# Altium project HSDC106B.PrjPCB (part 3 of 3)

## Sheet HSDC106B_EVM_DP83561_64p_EZFET.SchDoc
size 431 x 279 mm; Date: Not shown in title block; ApprovedBy: Not shown in title block; CheckedBy: Not shown in title block; Author: Not shown in title block; CompanyName: Not shown in title block; DrawnBy: Justin Lazaruk; Engineer: Not shown in title block; Organization: Not shown in title block; Address1: Not shown in title block; Address2: Not shown in title block; Address3: Not shown in title block; Address4: Not shown in title block; DocumentNumber: 8; Revision: Use project parameter SCH_Rev; SheetNumber: 8; SheetTotal: 9; PageSetup: Record=PageOptions¦CenterHorizontal=True¦CenterVertical=True¦PrintScale=1.00¦XCorrection=1.00¦YCorrection=1.00¦PrintKind=0¦BorderSize=5000000¦LeftOffset=0¦BottomOffset=0¦Orientation=2¦PaperLength=1000¦PaperWidth=1000¦Scale=100¦PaperSource=15¦PrintQuality=600¦MediaType=1¦DitherType=10¦PaperKind=Letter¦PrintScaleMode=1
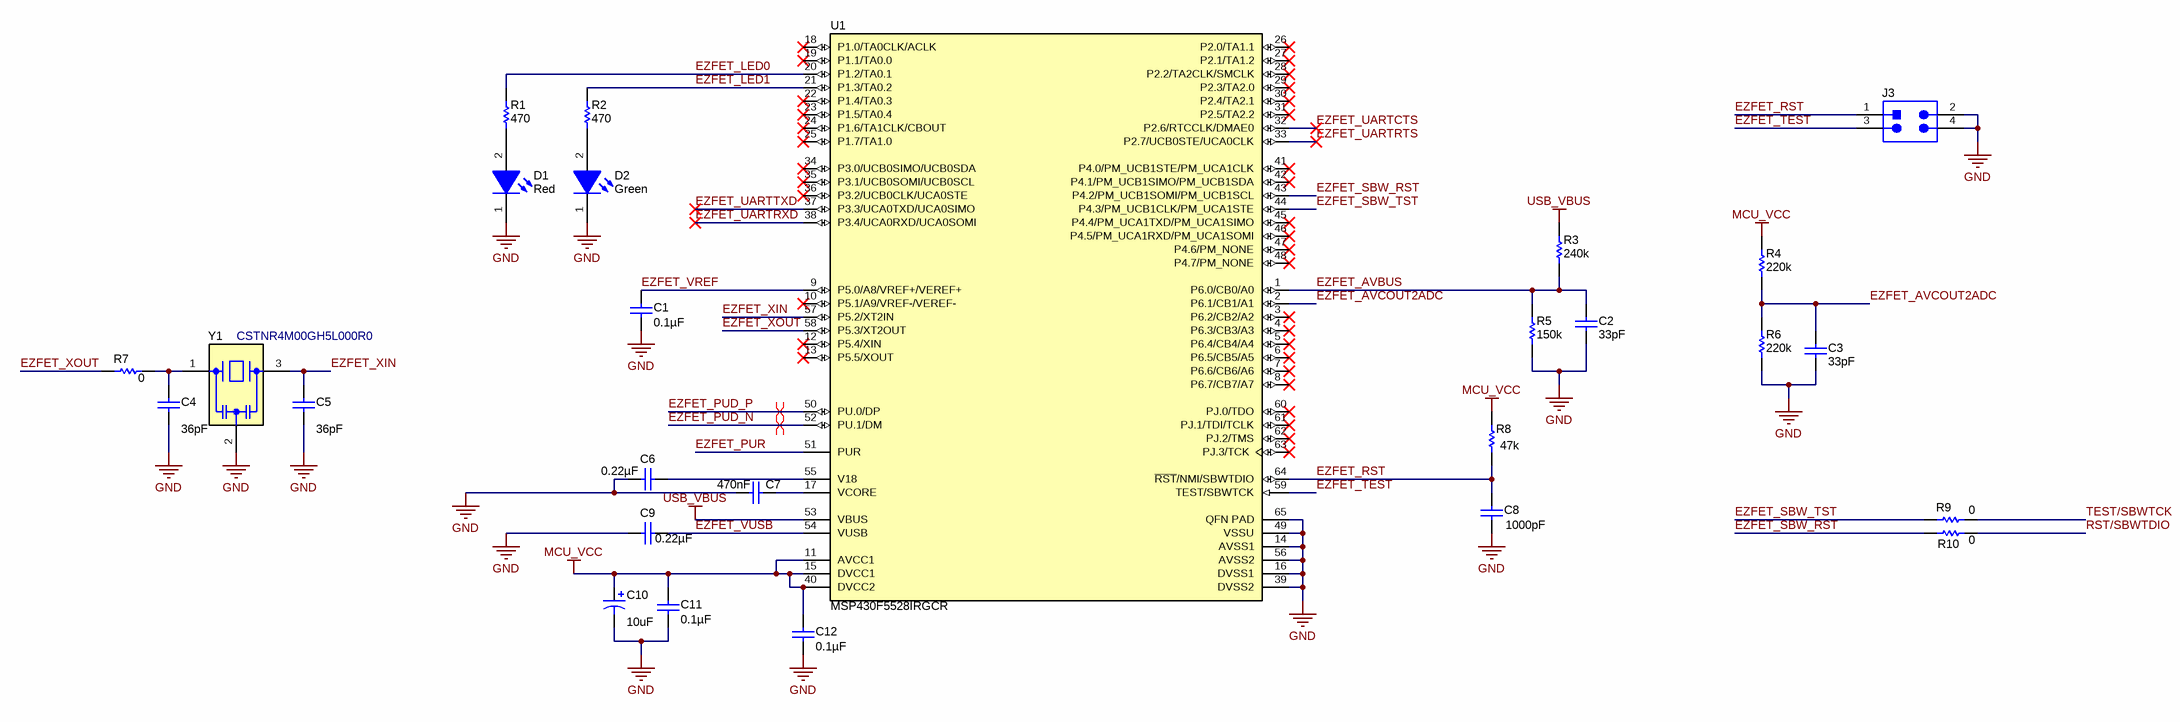
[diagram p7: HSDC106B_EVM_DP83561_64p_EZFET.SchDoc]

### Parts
C1  ValueDisplayed: 0.1µF  [0402]  (hidden comment: CL05B104KO5NNNC)
C2  ValueDisplayed: 33pF  [0402]  (hidden comment: 885012005043)
C3  ValueDisplayed: 33pF  [0402]  (hidden comment: 885012005043)
C4  ValueDisplayed: 36pF  [0402]  (hidden comment: CL05C360JB5NNNC)
C5  ValueDisplayed: 36pF  [0402]  (hidden comment: CL05C360JB5NNNC)
C6  ValueDisplayed: 0.22µF  [0603]  (hidden comment: CL10A224KB8NNNC)
C7  Cap_F: 470nF  [0603]  (hidden comment: CGA3E3X7R1H474K080AB)
C8  ValueDisplayed: 1000pF  [0402]  (hidden comment: GRM1555C1H102JA01D)
C9  ValueDisplayed: 0.22µF  [0603]  (hidden comment: CL10A224KB8NNNC)
C10  ValueDisplayed: 10uF  [7343-31]  (hidden comment: TPSD106K035R0125)
C11  ValueDisplayed: 0.1µF  [0402]  (hidden comment: CL05B104KO5NNNC)
C12  ValueDisplayed: 0.1µF  [0402]  (hidden comment: CL05B104KO5NNNC)
D1  value Red  [WL-SMCW_RED]  (hidden comment: 150060RS75000)
D2  value Green  [WL-SMCD-0603]  (hidden comment: 150060VS55040)
J3  TSW-102-07-G-D  [TSW-102-07-G-D]  (value not drawn)
R1  ValueDisplayed: 470  [0402]  (hidden comment: CRCW0402470RJNED)
R2  ValueDisplayed: 470  [0402]  (hidden comment: CRCW0402470RJNED)
R3  ValueDisplayed: 240k  [0402]  (hidden comment: CRCW0402240KJNED)
R4  ValueDisplayed: 220k  [0402]  (hidden comment: CRCW0402220KJNED)
R5  ValueDisplayed: 150k  [0402]  (hidden comment: CRCW0402150KJNED)
R6  ValueDisplayed: 220k  [0402]  (hidden comment: CRCW0402220KJNED)
R7  ValueDisplayed: 0  [0402]  (hidden comment: RC0402JR-070RL)
R8  ValueDisplayed: 47k  [0402]  (hidden comment: CRCW040247K0JNED)
R9  ValueDisplayed: 0  [0402]  (hidden comment: RC0402JR-070RL)
R10  ValueDisplayed: 0  [0402]  (hidden comment: RC0402JR-070RL)
U1  MSP430F5528IRGCR  [RGC0064B]
Y1  CSTNR4M00GH5L000R0  [MuRata_CSTNR]

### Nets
GND: C1.2 C2.2 C3.2 C4.2 C5.2 C6.2 C7.2 C8.2 C9.2 C10.2(-) C11.2 C12.2 D1.1(K) D2.1(K) J3.2 J3.4 R5.1 R6.1 U1.14(AVSS1) U1.16(DVSS1) U1.39(DVSS2) U1.49(VSSU) U1.56(AVSS2) U1.65(QFN_PAD) Y1.2(GND)
MCU_VCC: C10.1(+) C11.1 C12.1 R4.2 R8.2 U1.11(AVCC1) U1.15(DVCC1) U1.40(DVCC2)
USB_VBUS: R3.2 U1.53(VBUS)
EZFET_AVBUS: C2.1 R3.1 R5.2 U1.1(P6.0/CB0/A0)
EZFET_AVCOUT2ADC: C3.1 R4.1 R6.2 U1.2(P6.1/CB1/A1)
EZFET_LED0: R1.2 U1.20(P1.2/TA0.1)
EZFET_LED1: R2.2 U1.21(P1.3/TA0.2)
EZFET_PUD_N: U1.52(PU.1/DM)
EZFET_PUD_P: U1.50(PU.0/DP)
EZFET_PUR: U1.51(PUR)
EZFET_RST: C8.1 J3.1 R8.1 U1.64(~{RST}/NMI/SBWTDIO)
EZFET_SBW_RST: R10.1 U1.43(P4.2/PM_UCB1SOMI/PM_UCB1SCL)
EZFET_SBW_TST: R9.1 U1.44(P4.3/PM_UCB1CLK/PM_UCA1STE)
EZFET_TEST: J3.3 U1.59(TEST/SBWTCK)
EZFET_UARTCTS: U1.32(P2.6/RTCCLK/DMAE0)
EZFET_UARTRTS: U1.33(P2.7/UCB0STE/UCA0CLK)
EZFET_UARTRXD: U1.38(P3.4/UCA0RXD/UCA0SOMI)
EZFET_UARTTXD: U1.37(P3.3/UCA0TXD/UCA0SIMO)
EZFET_VREF: C1.1 U1.9(P5.0/A8/VREF+/VEREF+)
EZFET_VUSB: C9.1 U1.54(VUSB)
EZFET_XIN: C5.1 U1.57(P5.2/XT2IN) Y1.3(Out)
EZFET_XOUT: R7.1 U1.58(P5.3/XT2OUT)
RST/SBWTDIO: R10.2
TEST/SBWTCK: R9.2
NetC4_1: C4.1 R7.2 Y1.1(In)
NetC6_1: C6.1 U1.55(V18)
NetC7_1: C7.1 U1.17(VCORE)
NetD1_2: D1.2(A) R1.1
NetD2_2: D2.2(A) R2.1

Not connected (* = marked no-connect by the designer): U1 3(P6.2/CB2/A2)* 4(P6.3/CB3/A3)* 5(P6.4/CB4/A4)* 6(P6.5/CB5/A5)* 7(P6.6/CB6/A6)* 8(P6.7/CB7/A7)* 10(P5.1/A9/VREF-/VEREF-)* 12(P5.4/XIN)* 13(P5.5/XOUT)* 18(P1.0/TA0CLK/ACLK)* 19(P1.1/TA0.0)* 22(P1.4/TA0.3)* 23(P1.5/TA0.4)* 24(P1.6/TA1CLK/CBOUT)* 25(P1.7/TA1.0)* 26(P2.0/TA1.1)* 27(P2.1/TA1.2)* 28(P2.2/TA2CLK/SMCLK)* 29(P2.3/TA2.0)* 30(P2.4/TA2.1)* 31(P2.5/TA2.2)* 34(P3.0/UCB0SIMO/UCB0SDA)* 35(P3.1/UCB0SOMI/UCB0SCL)* 36(P3.2/UCB0CLK/UCA0STE)* 41(P4.0/PM_UCB1STE/PM_UCA1CLK)* 42(P4.1/PM_UCB1SIMO/PM_UCB1SDA)* 45(P4.4/PM_UCA1TXD/PM_UCA1SIMO)* 46(P4.5/PM_UCA1RXD/PM_UCA1SOMI)* 47(P4.6/PM_NONE)* 48(P4.7/PM_NONE)* 60(PJ.0/TDO)* 61(PJ.1/TDI/TCLK)* 62(PJ.2/TMS)* 63(PJ.3/TCK)*

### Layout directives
differential pair: EZFET_PUD_N, EZFET_PUD_P

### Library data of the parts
C1 C11 C12 = CMP-0085850-1: CAP, CERM, 0.1 µF, 16 V,+/- 10%, X7R, 0402; Manufacturer: Walsin; SizeZ_mm: 0.6; SizeX_mm: 1; AEC Category: Q200; AEC Qualified: N; SizeY_mm: 0.5; VDC_V: 16V; Value: 0.1uF; Cap_F: 100nF; U/M: EA; SizeAreaWB_mm2: 3; TaMin_C: -55°C; TaMax_C: 125°C
C2 C3 = CMP-0006213-2: CAP, CERM, 33 pF, 25 V, +/- 5%, C0G/NP0, 0402; Manufacturer: Wurth Elektronik; TaMin_C: -55°C; Polarized: N; SizeAreaWB_mm2: 3; Value1: Unknown; U/M: EA; Value: 33pF; TaMax_C: 125°C; SizeZ_mm: 0.6; SizeX_mm: 1; SizeY_mm: 0.5; Value2: 25V; AEC Category: Q200
C4 C5 = CMP-0083839-1: CAP, CERM, 36 pF, 50 V,+/- 5%, C0G/NP0, 0402; Manufacturer: Samsung Electro-Mechanics; SizeAreaWB_mm2: 3; SizeArea_mm2: 0.5; AEC Qualified: N; AEC Category: Q200; Value: 36pF; TaMax_C: 125°C; SizeZ_mm: 0.6; TaMin_C: -55°C; VDC_V: 50V; U/M: EA; SizeX_mm: 1
C6 C9 = CMP-0860899-1: CAP, CERM, 0.22 µF, 50 V,+/- 10%, X5R, 0603; Manufacturer: Samsung Electro-Mechanics; Cap_F: 220nF; U/M: EA; TaMax_C: 85°C; SizeAreaWB_mm2: 4.68; VDC_V: 50V; Value: 0.22uF; Polarized: N; AEC Category: Q200; SizeArea_mm2: 1.28; SizeY_mm: 0.8; SizeX_mm: 1.6; TaMin_C: -55°C; SizeZ_mm: 1
C7 = CMP-0007096-4: CAP, CERM, 0.47 uF, 50 V, +/- 10%, X7R, AEC-Q200 Grade 1, 0603; Manufacturer: TDK; TaMin_C: -55°C; ESR_ohm: 0.01064; Polarized: N; SizeAreaWB_mm2: 4.68; Value1: 0.01064 ohm; U/M: EA; Value: 0.47uF; TaMax_C: 125°C; SizeZ_mm: 1; SizeX_mm: 1.6; SizeY_mm: 0.8; Value2: 50V; SizeArea_mm2: 1.28; AEC Qualified: Y; IRMS_A: 1.59966A; AEC Category: Q200
C8 = CMP-0006412-2: CAP, CERM, 1000 pF, 50 V, +/- 5%, C0G/NP0, 0402; Manufacturer: MuRata; TaMin_C: -55°C; Polarized: N; SizeAreaWB_mm2: 3; Value1: Unknown; U/M: EA; Value: 1000pF; TaMax_C: 125°C; SizeZ_mm: 0.6; SizeX_mm: 1; SizeY_mm: 0.5; Value2: 50V; Cap_F: 1nF; AEC Category: Q200
C10 = CMP-0011855-2: CAP, TA, 10 uF, 35 V, +/- 10%, 0.125 ohm, SMD; Manufacturer: AVX; TaMin_C: -55°C; ESR_ohm: 0.125; Polarized: Y; SizeAreaWB_mm2: 58.59; U/M: EA; Value: 10uF; TaMax_C: 125°C; SizeZ_mm: 3.1; SizeX_mm: 7.3; SizeY_mm: 4.3; Cap_Case: D; Value2: 35V; SizeArea_mm2: 31.39; CompType: Capacitor; Cap_F: 10µF; IRMS_A: 986mA; AEC Category: Q200
D1 = CMP-0002947-3: LED, Red, SMD; Manufacturer: Wurth Elektronik; Value1: 0.072W; Vf_V: 2V; Angle: 140; Tjmax_C: 85°C; Type: AlInGaP; Vr_V: 5V; Io_A: 30mA; Power_TotalModule: 72mW
D2 = CMP-0081648-2: LED, Green, SMD; Manufacturer: Wurth Elektronik; Type: AlInGaP; Vr_V: 5V; SizeZ_mm: 0.5; Tjmax_C: 115°C; Io_A: 20mA; Value1: 0.048W; Vf_V: 2V; SizeArea_mm2: 1.28; Angle: 140; SizeX_mm: 1.6; Ir_A: 10µA; Power_TotalModule: 48mW; SizeAreaWB_mm2: 4.68; SizeY_mm: 0.8
J3 = CMP-0075404-1: Header, 100mil, 2x2, Gold, TH; Manufacturer: Samtec; Pitch_mm: 2.54; Cert_VDE: N; Gender: Male; Cert_CSA: Y; Voltage_V: 550V; Green_REACh: Passed; Current_A: 6.3A; CT: False; Green_Lifecycle: Active; Row_Count: 2; CNHeader: True
R1 R2 = CMP-0026934-3: RES, 470, 5%, 0.063 W, AEC-Q200 Grade 0, 0402; Manufacturer: Vishay-Dale; Power_W: 63mW; TempCo: 200 ppm/C; Value_Code: 470R; Value: 470; EIA_Code: E24; SizeX_mm: 1; SizeY_mm: 0.5; SizeZ_mm: 0.6; Value2: 0.063W; AEC Qualified: Y; VDC_V: 50V; AEC Category: Q200; AEC Grade: 0
R3 = CMP-0026881-2: RES, 240 k, 5%, 0.063 W, AEC-Q200 Grade 0, 0402; Manufacturer: Vishay-Dale; Power_W: 63mW; TempCo: 200 ppm/C; Value: 240k; EIA_Code: E24; SizeX_mm: 1; SizeY_mm: 0.5; SizeZ_mm: 0.6; Value2: 0.063W; AEC Qualified: Y; VDC_V: 50V; AEC Category: Q200; AEC Grade: 0
R4 R6 = CMP-0026877-2: RES, 220 k, 5%, 0.063 W, AEC-Q200 Grade 0, 0402; Manufacturer: Vishay-Dale; Power_W: 63mW; TempCo: 200 ppm/C; Value: 220k; EIA_Code: E24; SizeX_mm: 1; SizeY_mm: 0.5; SizeZ_mm: 0.6; Value2: 0.063W; AEC Qualified: Y; VDC_V: 50V; AEC Category: Q200; AEC Grade: 0
R5 = CMP-0026840-2: RES, 150 k, 5%, 0.063 W, AEC-Q200 Grade 0, 0402; Manufacturer: Vishay-Dale; Power_W: 63mW; TempCo: 200 ppm/C; Value: 150k; EIA_Code: E24; SizeX_mm: 1; SizeY_mm: 0.5; SizeZ_mm: 0.6; Value2: 0.063W; AEC Qualified: Y; VDC_V: 50V; AEC Category: Q200; AEC Grade: 0
R7 R9 R10 = CMP-0027004-2: RES, 0, 5%, 0.063 W, 0402; Manufacturer: Yageo America; Power_W: 63mW; TempCo: 200 ppm/C; Value_Code: 0000; U/M: EA; Value: 0; EIA_Code: E24; SizeX_mm: 1; SizeY_mm: 0.5; SizeZ_mm: 0.6; Value2: 0.063W; VDC_V: 50V; AEC Category: Q200
R8 = CMP-0026935-3: RES, 47 k, 5%, 0.063 W, AEC-Q200 Grade 0, 0402; Manufacturer: Vishay-Dale; Power_W: 63mW; TempCo: 200 ppm/C; Value_Code: 47k0; Value: 47k; EIA_Code: E24; SizeX_mm: 1; SizeY_mm: 0.5; SizeZ_mm: 0.6; Value2: 0.063W; AEC Qualified: Y; VDC_V: 50V; AEC Category: Q200; AEC Grade: 0
U1 = CMP-0039268-4: 16-Bit Ultra-Low-Power Microcontroller, 128KB Flash, 8KB RAM, USB, 12Bit ADC, 2 USCIs, 32Bit HW MPY, RGC0064B (VQFN-64); Manufacturer: Texas Instruments; ADC: 12-bit SAR; Flash(KB): 128; CompType: IC; USB: 1; Rating: Catalog; Frequency(MHz): 25; GPIO: 47; SVS: Yes; SizeAreaWB_mm2: 121.0; USCI_B (I2C & SPI): 2; DMA: 3; AEC Qualified: N; Timers - 16-bit: 4; SizeX_mm: 9.0; AEC Category: Q200; ADC Channels: 16; SizeArea_mm2: 81.0; Multiplier: 32x32; SRAM(B): 8192; SizeZ_mm: 1.0
Y1 = CMP-0085483-1: Oscillator, 4 MHz, 700 ppm, 39 pF, SMD; Manufacturer: MuRata; SizeArea_mm2: 9; Load Capacitance: 39 pF; SizeZ_mm: 1.2; AEC Category: Q200; Frequency Tolerance: 700 ppm; SizeX_mm: 4.5; SizeAreaWB_mm2: 16.5; TaMax_C: 85°C; TaMin_C: -20°C; SizeY_mm: 2; AEC Qualified: N; Frequency_Fixed: 4MHz

## Sheet HSDC106B_EVM_DP83561_64p_Breakout.SchDoc
size 431 x 279 mm; Date: Not shown in title block; ApprovedBy: Not shown in title block; CheckedBy: Not shown in title block; Author: Not shown in title block; CompanyName: Not shown in title block; DrawnBy: Justin Lazaruk; Engineer: Not shown in title block; Organization: Not shown in title block; Address1: Not shown in title block; Address2: Not shown in title block; Address3: Not shown in title block; Address4: Not shown in title block; DocumentNumber: 5; Revision: Use project parameter SCH_Rev; SheetNumber: 5; SheetTotal: 9; PageSetup: Record=PageOptions¦CenterHorizontal=True¦CenterVertical=True¦PrintScale=1.00¦XCorrection=1.00¦YCorrection=1.00¦PrintKind=0¦BorderSize=5000000¦LeftOffset=0¦BottomOffset=0¦Orientation=2¦PaperLength=1000¦PaperWidth=1000¦Scale=100¦PaperSource=15¦PrintQuality=600¦MediaType=1¦DitherType=10¦PaperKind=Letter¦PrintScaleMode=1
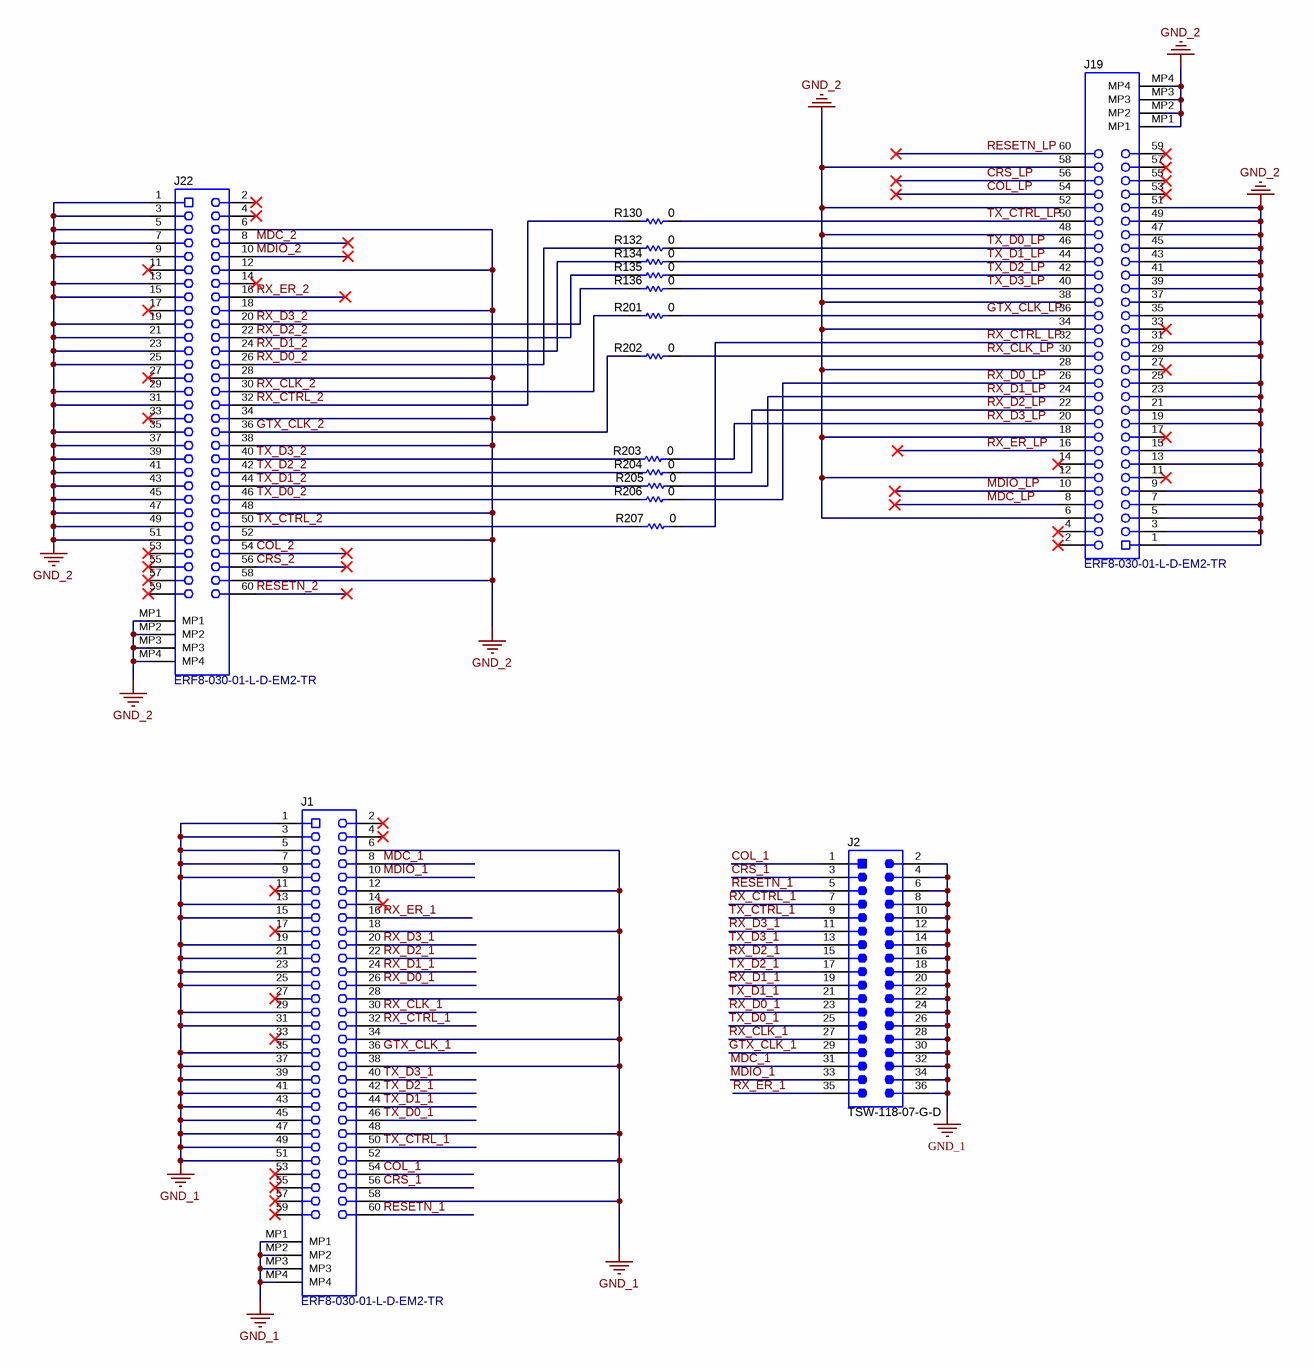
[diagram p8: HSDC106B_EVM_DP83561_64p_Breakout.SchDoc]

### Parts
J1  ERF8-030-01-L-D-EM2-TR  [Samtec_ERF8-030-01-x-D-EM2]
J2  TSW-118-07-G-D  [TSW-118-07-G-D]
J19  ERF8-030-01-L-D-EM2-TR  [Samtec_ERF8-030-01-x-D-EM2]
J22  ERF8-030-01-L-D-EM2-TR  [Samtec_ERF8-030-01-x-D-EM2]
R130  ValueDisplayed: 0  [0402]  (hidden comment: ERJ-2GE0R00X)
R132  ValueDisplayed: 0  [0402]  (hidden comment: ERJ-2GE0R00X)
R134  ValueDisplayed: 0  [0402]  (hidden comment: ERJ-2GE0R00X)
R135  ValueDisplayed: 0  [0402]  (hidden comment: ERJ-2GE0R00X)
R136  ValueDisplayed: 0  [0402]  (hidden comment: ERJ-2GE0R00X)
R201  ValueDisplayed: 0  [0402]  (hidden comment: ERJ-2GE0R00X)
R202  ValueDisplayed: 0  [0402]  (hidden comment: ERJ-2GE0R00X)
R203  ValueDisplayed: 0  [0402]  (hidden comment: ERJ-2GE0R00X)
R204  ValueDisplayed: 0  [0402]  (hidden comment: ERJ-2GE0R00X)
R205  ValueDisplayed: 0  [0402]  (hidden comment: ERJ-2GE0R00X)
R206  ValueDisplayed: 0  [0402]  (hidden comment: ERJ-2GE0R00X)
R207  ValueDisplayed: 0  [0402]  (hidden comment: ERJ-2GE0R00X)

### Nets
GND_1: J1.1 J1.3 J1.5 J1.6 J1.7 J1.9 J1.12 J1.13 J1.15 J1.18 J1.19 J1.21 J1.23 J1.25 J1.28 J1.29 J1.31 J1.34 J1.35 J1.37 J1.38 J1.39 J1.41 J1.43 J1.45 J1.47 J1.48 J1.49 J1.51 J1.52 J1.58 J1.MP1 J1.MP2 J1.MP3 J1.MP4 J2.2 J2.4 J2.6 J2.8 J2.10 J2.12 J2.14 J2.16 J2.18 J2.20 J2.22 J2.24 J2.26 J2.28 J2.30 J2.32 J2.34 J2.36
GND_2: J19.1 J19.3 J19.5 J19.6 J19.7 J19.9 J19.12 J19.13 J19.15 J19.18 J19.19 J19.21 J19.23 J19.25 J19.28 J19.29 J19.31 J19.34 J19.35 J19.37 J19.38 J19.39 J19.41 J19.43 J19.45 J19.47 J19.48 J19.49 J19.51 J19.52 J19.58 J19.MP1 J19.MP2 J19.MP3 J19.MP4 J22.1 J22.3 J22.5 J22.6 J22.7 J22.9 J22.12 J22.13 J22.15 J22.18 J22.19 J22.21 J22.23 J22.25 J22.28 J22.29 J22.31 J22.34 J22.35 J22.37 J22.38 J22.39 J22.41 J22.43 J22.45 J22.47 J22.48 J22.49 J22.51 J22.52 J22.58 J22.MP1 J22.MP2 J22.MP3 J22.MP4
COL_1: J1.54 J2.1
COL_2: J22.54
COL_LP: J19.54
CRS_1: J1.56 J2.3
CRS_2: J22.56
CRS_LP: J19.56
GTX_CLK_1: J1.36 J2.29
GTX_CLK_2: J22.36 R202.1
GTX_CLK_LP: J19.36 R201.2
MDC_1: J1.8 J2.31
MDC_2: J22.8
MDC_LP: J19.8
MDIO_1: J1.10 J2.33
MDIO_2: J22.10
MDIO_LP: J19.10
RESETN_1: J1.60 J2.5
RESETN_2: J22.60
RESETN_LP: J19.60
RX_CLK_1: J1.30 J2.27
RX_CLK_2: J22.30 R201.1
RX_CLK_LP: J19.30 R202.2
RX_CTRL_1: J1.32 J2.7
RX_CTRL_2: J22.32 R130.1
RX_CTRL_LP: J19.32 R207.2
RX_D0_1: J1.26 J2.23
RX_D0_2: J22.26 R132.1
RX_D0_LP: J19.26 R206.2
RX_D1_1: J1.24 J2.19
RX_D1_2: J22.24 R134.1
RX_D1_LP: J19.24 R205.2
RX_D2_1: J1.22 J2.15
RX_D2_2: J22.22 R135.1
RX_D2_LP: J19.22 R204.2
RX_D3_1: J1.20 J2.11
RX_D3_2: J22.20 R136.1
RX_D3_LP: J19.20 R203.2
RX_ER_1: J1.16 J2.35
RX_ER_2: J22.16
RX_ER_LP: J19.16
TX_CTRL_1: J1.50 J2.9
TX_CTRL_2: J22.50 R207.1
TX_CTRL_LP: J19.50 R130.2
TX_D0_1: J1.46 J2.25
TX_D0_2: J22.46 R206.1
TX_D0_LP: J19.46 R132.2
TX_D1_1: J1.44 J2.21
TX_D1_2: J22.44 R205.1
TX_D1_LP: J19.44 R134.2
TX_D2_1: J1.42 J2.17
TX_D2_2: J22.42 R204.1
TX_D2_LP: J19.42 R135.2
TX_D3_1: J1.40 J2.13
TX_D3_2: J22.40 R203.1
TX_D3_LP: J19.40 R136.2

Not connected (* = marked no-connect by the designer): J1 2* 4* 11* 14* 17* 27* 33* 53* 55* 57* 59*; J19 2* 4* 11* 14* 17* 27* 33* 53* 55* 57* 59*; J22 2* 4* 11* 14* 17* 27* 33* 53* 55* 57* 59*

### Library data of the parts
J1 J19 J22 = CMP-0055720-1: Receptacle, 0.8mm, 30x2, Gold, Edge Mount; Manufacturer: Samtec; CNHeader: FALSE; Current_A: 2.2A; Gender: Female; Voltage_V: 200V; CompType: Card Edge Socket; Row_Count: 2; Pitch_mm: 0.8; CT: TRUE; Cert_UL: Y
J2 = CMP-0075431-1: Header, 100mil, 18x2, Gold, TH; Manufacturer: Samtec; Pitch_mm: 2.54; Cert_VDE: N; Gender: Male; Cert_CSA: Y; Voltage_V: 550V; Green_REACh: Passed; Current_A: 6.3A; CT: False; Green_Lifecycle: Active; Row_Count: 2; CNHeader: True
R130 R132 R134-R136 R201-R207 = CMP-0026992-3: RES, 0, 5%, 0.1 W, AEC-Q200 Grade 0, 0402; Manufacturer: Panasonic; Power_W: 100mW; TempCo: 600 ppm/C; Value_Code: 0000; Value: 0; EIA_Code: E24; SizeX_mm: 1; SizeY_mm: 0.5; SizeZ_mm: 0.6; Value2: 0.1W; AEC Qualified: Y; VDC_V: 50V; AEC Category: Q200; SizeAreaWB_mm2: 3

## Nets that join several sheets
GND: HSDC106B_EVM_DP83561_64p_USB (43 pins), HSDC106B_EVM_DP83561_64p_Straps (8 pins), HSDC106B_EVM_DP83561_64p_PowerSupply (60 pins), HSDC106B_EVM_DP83561_64p_PHY (51 pins), HSDC106B_EVM_DP83561_64p_MSP430 (41 pins), HSDC106B_EVM_DP83561_64p_MAC_RJ45 (56 pins), HSDC106B_EVM_DP83561_64p_Hardware (7 pins), HSDC106B_EVM_DP83561_64p_EZFET (25 pins)
MCU_VCC: HSDC106B_EVM_DP83561_64p_USB (15 pins), HSDC106B_EVM_DP83561_64p_MSP430 (21 pins), HSDC106B_EVM_DP83561_64p_EZFET (8 pins)
RJ45_ERTH: HSDC106B_EVM_DP83561_64p_MAC_RJ45 (9 pins), HSDC106B_EVM_DP83561_64p_Hardware (M8.1)
USB_VBUS: HSDC106B_EVM_DP83561_64p_USB (5 pins), HSDC106B_EVM_DP83561_64p_PowerSupply (J21.1), HSDC106B_EVM_DP83561_64p_MSP430 (C19.2 U4.65), HSDC106B_EVM_DP83561_64p_EZFET (R3.2 U1.53)
VDDIO: HSDC106B_EVM_DP83561_64p_Straps (19 pins), HSDC106B_EVM_DP83561_64p_PowerSupply (5 pins), HSDC106B_EVM_DP83561_64p_PHY (17 pins), HSDC106B_EVM_DP83561_64p_MSP430 (R47.2 R48.2 R51.2)
AUTO_RECOVER: HSDC106B_EVM_DP83561_64p_Straps (J39.1), HSDC106B_EVM_DP83561_64p_PHY (J8.10 U5.34)
COL: HSDC106B_EVM_DP83561_64p_PHY (U5.32), HSDC106B_EVM_DP83561_64p_MAC_RJ45 (J6.1 R32.1)
CRS: HSDC106B_EVM_DP83561_64p_Straps (J41.1), HSDC106B_EVM_DP83561_64p_PHY (U5.33), HSDC106B_EVM_DP83561_64p_MAC_RJ45 (R33.1)
EZFET_PUD_N: HSDC106B_EVM_DP83561_64p_USB (C128.1 R196.1), HSDC106B_EVM_DP83561_64p_EZFET (U1.52)
EZFET_PUD_P: HSDC106B_EVM_DP83561_64p_USB (C127.1 R197.1 R199.1 R200.2), HSDC106B_EVM_DP83561_64p_EZFET (U1.50)
EZFET_PUR: HSDC106B_EVM_DP83561_64p_USB (R197.2), HSDC106B_EVM_DP83561_64p_EZFET (U1.51)
EZFET_UARTRXD: HSDC106B_EVM_DP83561_64p_MSP430 (U4.51), HSDC106B_EVM_DP83561_64p_EZFET (U1.38)
EZFET_UARTTXD: HSDC106B_EVM_DP83561_64p_MSP430 (U4.52), HSDC106B_EVM_DP83561_64p_EZFET (U1.37)
GTX_CLK: HSDC106B_EVM_DP83561_64p_PHY (U5.39), HSDC106B_EVM_DP83561_64p_MAC_RJ45 (R20.1)
INT_PWDN: HSDC106B_EVM_DP83561_64p_PHY (J8.12 J15.2 U5.60), HSDC106B_EVM_DP83561_64p_MSP430 (R55.1)
JTAG_TDO: HSDC106B_EVM_DP83561_64p_Straps (J34.1), HSDC106B_EVM_DP83561_64p_PHY (P1.6 R88.2 U5.29)
LED0: HSDC106B_EVM_DP83561_64p_Straps (J28.2), HSDC106B_EVM_DP83561_64p_PHY (U5.63)
LED1: HSDC106B_EVM_DP83561_64p_Straps (J33.2), HSDC106B_EVM_DP83561_64p_PHY (U5.62)
LED2: HSDC106B_EVM_DP83561_64p_Straps (J38.2), HSDC106B_EVM_DP83561_64p_PHY (U5.61)
MDC: HSDC106B_EVM_DP83561_64p_PHY (U5.54), HSDC106B_EVM_DP83561_64p_MSP430 (J43.3 R48.1 R54.1 U3.3), HSDC106B_EVM_DP83561_64p_MAC_RJ45 (R11.1)
MDIO: HSDC106B_EVM_DP83561_64p_PHY (R85.2 U5.53), HSDC106B_EVM_DP83561_64p_MSP430 (J43.2 R56.1 U3.4), HSDC106B_EVM_DP83561_64p_MAC_RJ45 (R12.1)
RESET_N: HSDC106B_EVM_DP83561_64p_PHY (6 pins), HSDC106B_EVM_DP83561_64p_MSP430 (R57.1), HSDC106B_EVM_DP83561_64p_MAC_RJ45 (R34.1)
RST/SBWTDIO: HSDC106B_EVM_DP83561_64p_MSP430 (5 pins), HSDC106B_EVM_DP83561_64p_EZFET (R10.2)
RX_CLK: HSDC106B_EVM_DP83561_64p_Straps (J32.1), HSDC106B_EVM_DP83561_64p_PHY (U5.42), HSDC106B_EVM_DP83561_64p_MAC_RJ45 (R18.1)
RX_CTRL: HSDC106B_EVM_DP83561_64p_Straps (J31.1), HSDC106B_EVM_DP83561_64p_PHY (U5.49), HSDC106B_EVM_DP83561_64p_MAC_RJ45 (R19.1)
RX_D0: HSDC106B_EVM_DP83561_64p_Straps (R152.1 R154.2), HSDC106B_EVM_DP83561_64p_PHY (U5.44), HSDC106B_EVM_DP83561_64p_MAC_RJ45 (R17.1)
RX_D1: HSDC106B_EVM_DP83561_64p_Straps (R155.1 R158.2), HSDC106B_EVM_DP83561_64p_PHY (U5.45), HSDC106B_EVM_DP83561_64p_MAC_RJ45 (R16.1)
RX_D2: HSDC106B_EVM_DP83561_64p_Straps (J29.1), HSDC106B_EVM_DP83561_64p_PHY (U5.46), HSDC106B_EVM_DP83561_64p_MAC_RJ45 (R15.1)
RX_D3: HSDC106B_EVM_DP83561_64p_Straps (J30.1), HSDC106B_EVM_DP83561_64p_PHY (U5.47), HSDC106B_EVM_DP83561_64p_MAC_RJ45 (R14.1)
RX_ER: HSDC106B_EVM_DP83561_64p_PHY (U5.43), HSDC106B_EVM_DP83561_64p_MAC_RJ45 (J5.1 R13.1)
SMI_DISABLE: HSDC106B_EVM_DP83561_64p_Straps (J40.1), HSDC106B_EVM_DP83561_64p_PHY (U5.50)
SUPPLYMODESEL: HSDC106B_EVM_DP83561_64p_Straps (J37.1), HSDC106B_EVM_DP83561_64p_PHY (U5.23)
TARGET_D_N: HSDC106B_EVM_DP83561_64p_USB (C123.1 R180.1), HSDC106B_EVM_DP83561_64p_MSP430 (U4.64)
TARGET_D_P: HSDC106B_EVM_DP83561_64p_USB (C122.1 R183.1), HSDC106B_EVM_DP83561_64p_MSP430 (R73.2 U4.62)
TD_A_N: HSDC106B_EVM_DP83561_64p_PHY (U5.3), HSDC106B_EVM_DP83561_64p_MAC_RJ45 (R122.2 R124.2)
TD_A_P: HSDC106B_EVM_DP83561_64p_PHY (U5.2), HSDC106B_EVM_DP83561_64p_MAC_RJ45 (R119.2 R120.2)
TD_B_N: HSDC106B_EVM_DP83561_64p_PHY (U5.6), HSDC106B_EVM_DP83561_64p_MAC_RJ45 (R131.2 R133.2)
TD_B_P: HSDC106B_EVM_DP83561_64p_PHY (U5.5), HSDC106B_EVM_DP83561_64p_MAC_RJ45 (R127.2 R129.2)
TD_C_N: HSDC106B_EVM_DP83561_64p_PHY (U5.11), HSDC106B_EVM_DP83561_64p_MAC_RJ45 (R139.2 R140.2)
TD_C_P: HSDC106B_EVM_DP83561_64p_PHY (U5.10), HSDC106B_EVM_DP83561_64p_MAC_RJ45 (R137.2 R138.2)
TD_D_N: HSDC106B_EVM_DP83561_64p_PHY (U5.14), HSDC106B_EVM_DP83561_64p_MAC_RJ45 (R143.2 R144.2)
TD_D_P: HSDC106B_EVM_DP83561_64p_PHY (U5.13), HSDC106B_EVM_DP83561_64p_MAC_RJ45 (R141.2 R142.2)
TEST/SBWTCK: HSDC106B_EVM_DP83561_64p_MSP430 (J9.1 U4.71), HSDC106B_EVM_DP83561_64p_EZFET (R9.2)
TX_CTRL: HSDC106B_EVM_DP83561_64p_PHY (U5.48), HSDC106B_EVM_DP83561_64p_MAC_RJ45 (R31.1)
TX_D0: HSDC106B_EVM_DP83561_64p_PHY (U5.38), HSDC106B_EVM_DP83561_64p_MAC_RJ45 (R29.1)
TX_D1: HSDC106B_EVM_DP83561_64p_PHY (U5.37), HSDC106B_EVM_DP83561_64p_MAC_RJ45 (R27.1)
TX_D2: HSDC106B_EVM_DP83561_64p_PHY (U5.36), HSDC106B_EVM_DP83561_64p_MAC_RJ45 (R25.1)
TX_D3: HSDC106B_EVM_DP83561_64p_PHY (U5.35), HSDC106B_EVM_DP83561_64p_MAC_RJ45 (R23.1)
VDD1P0: HSDC106B_EVM_DP83561_64p_PowerSupply (C77.2 J17.2 J24.2), HSDC106B_EVM_DP83561_64p_PHY (9 pins)
VDDA1P8_AB: HSDC106B_EVM_DP83561_64p_PowerSupply (C75.2 R97.2), HSDC106B_EVM_DP83561_64p_PHY (C38.2 C39.2 U5.16)
VDDA1P8_CD: HSDC106B_EVM_DP83561_64p_PowerSupply (C76.2 R99.2), HSDC106B_EVM_DP83561_64p_PHY (C36.2 C37.2 U5.64)
VDDA2P5: HSDC106B_EVM_DP83561_64p_PowerSupply (C74.2 J17.4 J20.2), HSDC106B_EVM_DP83561_64p_PHY (6 pins)
VDDIOSEL_0: HSDC106B_EVM_DP83561_64p_Straps (J36.1), HSDC106B_EVM_DP83561_64p_PHY (U5.22)
VDDIOSEL_1: HSDC106B_EVM_DP83561_64p_Straps (J35.1), HSDC106B_EVM_DP83561_64p_PHY (U5.21)

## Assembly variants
001: not fitted C53 C71 C81 C87 C95 C97 C99 C101 C103 C104 C106 C107 FID1 FID2 FID3 FID4 FID5 FID6 FID7 FID8 FID9 FID10 FID11 FID12 FID13 FID14 FID15 FID16 FID17 FID18 R39 R47 R49 R50 R52 R53 R54 R55 R56 R57 R84 R88 R120 R124 R129 R133 R138 R140 R142 R144 R152 R154 R155 R158 U11 U12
